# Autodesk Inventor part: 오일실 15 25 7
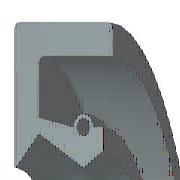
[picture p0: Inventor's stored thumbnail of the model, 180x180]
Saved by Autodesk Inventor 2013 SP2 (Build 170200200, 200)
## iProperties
Created: 2012-02
Part Number: 오일실 15 25 7
Material: 고무
Description: 오일-실
Document SubType Name: Modeling
Standard: KS B 2804
Designer: mduedu
Standards Organization: KS
Language: ko-KR
Size Designation: D - 15 25 7
Categories: <MemberInstance><Categories><Category DisplayName="샤프트 부품" InternalName="7f7aeb1f-a693-4053-b835-cee3144e0d98" Mnemonic="SHFT"><Category DisplayName="실링" Intern
Density: 0.93 g/cm^3
IsCustomPart: 1
Author: mduedu
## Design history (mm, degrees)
revolve "본체" stored, may be unused: angle "d17" = 90 deg
revolve "스프링1" stored, may be unused: angle "d18" = 90 deg
body "Solid1"
sketch "스케치1"
  geometry: L1 (0, 12.5)-(7, 12.5); L2 (7, 10.75)-(1.75, 10.75); L3 (1.75, 9.25)-(4.9, 7.5); L4 (4.9, 7.5)-(0, 7.5); L5 (0, 0)-(9.586, 0) reference; L6 (4.9, 7.5)-(6.3, 8.375); L7 (0, 18)-(0, -3) reference; L8 (-1.941, 0)-(11.507, 0) reference; L9 (4.2, 9.6)-(1.75, 10.09); L10 (1.75, 10.09)-(1.75, 10.75); L11 (0, 12.5)-(0, 7.588); L12 (4.9, 7.5)-(0, 7.5); L13 (1.75, 9.25)-(0.152, 7.528); L14 (7, 12.5)-(7, 10.75); L15 (5.6, 9.6)-(6.3, 9.6); L16 (6.3, 9.6)-(6.3, 8.375); C1 r 0.455 at (4.9, 9.6); A1 r 0.7 centre (4.9, 9.6) between (5.6, 9.6) and (4.2, 9.6); A2 r 0.088 centre (0.088, 7.588) between (0, 7.588) and (0.152, 7.528); 1 further point
  constraints: 28 end point, 5 horizontal alignment, 5 point on line, 4 point on circle, 4 vertical alignment, 3 centre point, 3 tangent, 2 collinear, 2 horizontal, 2 perpendicular, 1 coincident, 1 parallel
  dimensions: "d0" = 25 diameter of L1 L5 (= SD2); "d1" = 1.75 distance of L1.end L2.start (= SD); "d2" = 0.91 diameter of C1 (= SPDI); "d3" = 1.4 diameter of A1 (= SPDA); "d4" = 15 diameter of L3.end L5 (= NND); "d5" = 18.5 diameter of L3.start L5 (= TKDM); "d7" = 20.18 diameter of L9.end L5 (= TKDM + 0.24 x SWDT); "d8" = 1.75 distance between parallel lines of L11 L10 (= SD); "d9" = 4.9 distance from line of L11 C1.centre (= SPDST); "d10" = 19.2 diameter of C1.centre L5 (= HLDM); "d11" = 0.0875 radius of A2 (= 0.25 x LAB); "d12" = 6.3 distance between parallel lines of L11 L16 (= SDI); "d13" = 16.75 diameter of L6.end L5 (= ABDM); "d14" = 7 distance from line of L11 L1.end (= SWDT)
fillet "모깎기1" dims "d6" = 0.3 (= RR)
other parameters: "SD2" = 25 [user parameter; used in 1 equation term], "SWDT" = 7 [user parameter; used in 2 equation terms], "RR" = 0.3 [user parameter; used in 1 equation term], "SD" = 1.75 [user parameter; used in 2 equation terms], "NND" = 15 [user parameter; used in 1 equation term], "SPDA" = 1.4 [user parameter; used in 1 equation term], "SPDI" = 0.91 [user parameter; used in 1 equation term], "TKDM" = 18.5 [user parameter; used in 2 equation terms], "HLDM" = 19.2 [user parameter; used in 1 equation term], "ABDM" = 16.75 [user parameter; used in 1 equation term], "SDI" = 6.3 [user parameter; used in 1 equation term], "SPDST" = 4.9 [user parameter; used in 1 equation term], "LAB" = 0.35 [user parameter; used in 1 equation term], "d15" = 0, "d16" = 0, "d19" = 0
